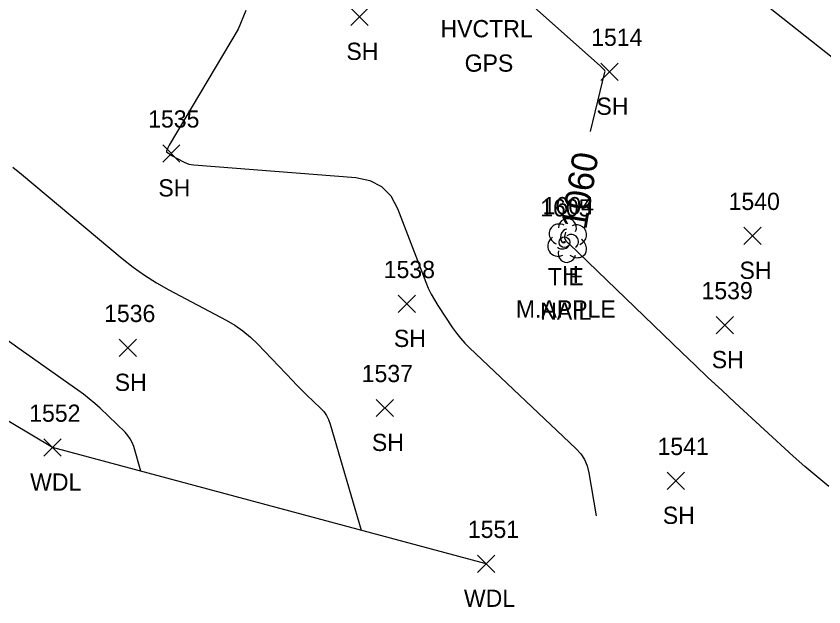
# Model space of a CAD drawing. Extents: x 1592612 to 1596497, y 111838 to 113741.
# Drawn here: x 1593027 to 1593120.8, y 113293.5 to 113362.1 of the extents above; entities that cross this region are included whole.
import ezdxf

# ---------------------------------------------------------------- set-up
doc = ezdxf.new("R2010")
doc.units = 0
for name, color, linetype in [('C_A', 7, 'Continuous'), ('C_C', 7, 'Continuous'), ('C_I', 7, 'Continuous'), ('CBP', 7, 'Continuous'), ('L_A', 7, 'Continuous'), ('L_C', 7, 'Continuous'), ('L_I', 7, 'Continuous'), ('L_TIC', 7, 'Continuous'), ('LAWA', 7, 'Continuous'), ('LSOGCMA', 7, 'Continuous'), ('LSOGCMA_T', 7, 'Continuous'), ('LSOGCMI', 7, 'Continuous'), ('LTD', 7, 'Continuous')]:
    doc.layers.add(name, color=color, linetype=linetype)

msp = doc.modelspace()

# ---------------------------------------------------------------- linework, layer by layer
at = {"layer": 'CBP'}
for radius in [0.625, 0.0833]:
    msp.add_circle((1593090.649, 113335.832), radius, dxfattribs=at)
at = {"layer": 'L_TIC'}
for points in [[(1593065.844, 113361.005), (1593067.844, 113363.005)], [(1593067.844, 113361.005), (1593065.844, 113363.005)], [(1593094.872, 113354.632), (1593096.872, 113356.632)], [(1593096.872, 113354.632), (1593094.872, 113356.632)], [(1593044.013, 113345.147), (1593046.013, 113347.147)], [(1593046.013, 113345.147), (1593044.013, 113347.147)], [(1593111.481, 113335.579), (1593113.481, 113337.579)], [(1593113.481, 113335.579), (1593111.481, 113337.579)], [(1593071.36, 113327.669), (1593073.36, 113329.669)], [(1593073.36, 113327.669), (1593071.36, 113329.669)], [(1593108.257, 113325.209), (1593110.257, 113327.209)], [(1593110.257, 113325.209), (1593108.257, 113327.209)], [(1593038.953, 113322.567), (1593040.953, 113324.567)], [(1593040.953, 113322.567), (1593038.953, 113324.567)], [(1593068.803, 113315.59), (1593070.803, 113317.59)], [(1593070.803, 113315.59), (1593068.803, 113317.59)], [(1593030.204, 113310.984), (1593032.204, 113312.984)], [(1593032.204, 113310.984), (1593030.204, 113312.984)], [(1593102.573, 113307.124), (1593104.573, 113309.124)], [(1593104.573, 113307.124), (1593102.573, 113309.124)], [(1593080.556, 113297.492), (1593082.556, 113299.492)], [(1593082.556, 113297.492), (1593080.556, 113299.492)]]:
    msp.add_lwpolyline(points, dxfattribs=at)
at = {"layer": 'LAWA'}
msp.add_lwpolyline([(1593081.556, 113298.492), (1593031.204, 113311.984), (1593004.196, 113328.084), (1592975.03, 113331.936), (1592955.15, 113341.657), (1592943.474, 113365.084), (1592935.771, 113387.596), (1592932.916, 113413.656)], dxfattribs=at)
at = {"layer": 'LSOGCMA'}
for points in [[(1593093.66, 113348.705), (1593095.344, 113355.593), (1593095.353, 113355.664), (1593095.344, 113355.73), (1593095.317, 113355.791), (1593095.272, 113355.846), (1593095.056, 113356.059), (1593095.002, 113356.111), (1593094.947, 113356.163), (1593094.892, 113356.215), (1593094.835, 113356.265), (1593081.553, 113368.117)], [(1593121.327, 113307.471), (1593119.927, 113308.618), (1593118.554, 113309.797), (1593117.206, 113311.006), (1593110.465, 113317.194), (1593108.902, 113318.638), (1593107.347, 113320.092), (1593105.8, 113321.556), (1593104.263, 113323.028), (1593091.183, 113335.635), (1593091.148, 113335.67), (1593091.112, 113335.704), (1593091.076, 113335.738), (1593091.04, 113335.772), (1593090.835, 113335.966), (1593090.83, 113335.971), (1593090.825, 113335.976), (1593090.821, 113335.982), (1593090.817, 113335.988), (1593090.801, 113336.012), (1593090.797, 113336.018), (1593090.794, 113336.024), (1593090.79, 113336.031), (1593090.788, 113336.037), (1593090.685, 113336.303), (1593090.671, 113336.35), (1593090.664, 113336.397), (1593090.665, 113336.445), (1593090.673, 113336.493), (1593090.801, 113337.014)]]:
    msp.add_lwpolyline(points, dxfattribs=at)
at = {"layer": 'LSOGCMI'}
for points in [[(1593113.604, 113363.735), (1593125.992, 113353.948)], [(1593053.675, 113362.732), (1593052.782, 113360.581), (1593044.775, 113347.096), (1593044.733, 113347.022), (1593044.692, 113346.947), (1593044.653, 113346.872), (1593044.617, 113346.795), (1593044.444, 113346.422), (1593044.431, 113346.38), (1593044.435, 113346.342), (1593044.454, 113346.31), (1593044.489, 113346.283), (1593044.684, 113346.172), (1593044.715, 113346.154), (1593044.745, 113346.134), (1593044.774, 113346.113), (1593044.803, 113346.09), (1593044.914, 113345.997), (1593044.942, 113345.975), (1593044.972, 113345.954), (1593045.002, 113345.934), (1593045.034, 113345.916), (1593046.519, 113345.129), (1593046.781, 113345.006), (1593047.051, 113344.912), (1593047.33, 113344.846), (1593047.618, 113344.809), (1593066.425, 113343.342), (1593068.06, 113343.013), (1593069.41, 113342.303), (1593070.476, 113341.211), (1593071.258, 113339.739), (1593074.543, 113331.201), (1593074.839, 113330.491), (1593075.172, 113329.8), (1593075.543, 113329.129), (1593075.952, 113328.477), (1593077.66, 113325.908), (1593078.103, 113325.279), (1593078.581, 113324.679), (1593079.091, 113324.107), (1593079.635, 113323.563), (1593091.983, 113311.881), (1593092.536, 113311.27), (1593092.971, 113310.597), (1593093.288, 113309.861), (1593093.486, 113309.062), (1593094.325, 113304.078)], [(1593026.597, 113344.543), (1593027.623, 113343.723), (1593039.288, 113333.962), (1593040.573, 113332.942), (1593041.905, 113331.994), (1593043.286, 113331.117), (1593044.714, 113330.311), (1593051.36, 113326.785), (1593052.366, 113326.2), (1593053.314, 113325.539), (1593054.206, 113324.804), (1593055.042, 113323.994), (1593059.107, 113319.724), (1593059.498, 113319.319), (1593059.893, 113318.918), (1593060.293, 113318.522), (1593060.698, 113318.13), (1593062.327, 113316.574), (1593062.703, 113316.165), (1593063.016, 113315.719), (1593063.268, 113315.235), (1593063.456, 113314.714), (1593067.05, 113302.379)], [(1593041.481, 113309.23), (1593040.641, 113312.115), (1593040.473, 113312.579), (1593040.249, 113313.009), (1593039.971, 113313.406), (1593039.636, 113313.769), (1593036.732, 113316.545), (1593036.117, 113317.111), (1593035.483, 113317.653), (1593034.828, 113318.171), (1593034.154, 113318.665), (1593027.189, 113323.573), (1593025.812, 113324.567)]]:
    msp.add_lwpolyline(points, dxfattribs=at)
at = {"layer": 'LTD'}
msp.add_line((1593090.941, 113336.083), (1593090.941, 113336.083), dxfattribs=at)
msp.add_line((1593090.941, 113336.083), (1593090.941, 113336.083), dxfattribs=at)
msp.add_arc((1593090.988, 113337.517), 1.047, 335.52715, 180.95627, dxfattribs=at)
for centre, major_axis, ratio, start_param, end_param in [((1593090.149, 113336.749), (1.21, -0.512), 0.895232, 1.570796, 4.712389), ((1593091.982, 113336.666), (-1.141, -0.483), 0.949671, 1.570796, 4.712389), ((1593090.732, 113336.541), (-0.208, -0.792), 0.645439, 3.141593, 6.283185), ((1593091.441, 113335.916), (-0.5, 0.667), 0.989748, 3.141593, 6.283185), ((1593089.858, 113335.374), (0.584, -1.042), 0.959034, 3.141593, 6.283185), ((1593091.941, 113335.25), (-1.09, 0.792), 0.841452, 1.570796, 4.712389), ((1593090.483, 113335.333), (-0.625, -0.083), 0.423636, 0, 3.141593), ((1593090.941, 113334.583), (0.265, 1.061), 0.942809, 1.570796, 4.712389)]:
    msp.add_ellipse(centre, major_axis=major_axis, ratio=ratio, start_param=start_param, end_param=end_param, dxfattribs=at)

# ---------------------------------------------------------------- texts
at = {"layer": 'C_A'}
for s, p in [('HVCTRL', (1593076.256, 113359.637)), ('HVCTRL', (1593076.265, 113359.633)), ('TIE', (1593088.728, 113330.832))]:
    msp.add_text(s, height=2, dxfattribs=at).set_placement(p)
at = {"layer": 'C_C'}
for s, p in [('GPS', (1593079.059, 113355.637)), ('NAIL', (1593087.83, 113326.832))]:
    msp.add_text(s, height=2, dxfattribs=at).set_placement(p)
at = {"layer": 'C_I'}
msp.add_text('1605', height=2, dxfattribs=at).set_placement((1593087.83, 113338.832))
at = {"layer": 'L_A'}
for s, p in [('SH', (1593065.333, 113357.005)), ('SH', (1593094.36, 113350.632)), ('SH', (1593043.502, 113341.147)), ('SH', (1593110.969, 113331.579)), ('H', (1593090.374, 113331.083)), ('SH', (1593070.848, 113323.669)), ('SH', (1593107.745, 113321.209)), ('SH', (1593038.441, 113318.567)), ('SH', (1593068.291, 113311.59)), ('WDL', (1593028.621, 113306.984)), ('SH', (1593102.061, 113303.124)), ('WDL', (1593078.973, 113293.492))]:
    msp.add_text(s, height=2, dxfattribs=at).set_placement(p)
at = {"layer": 'L_C'}
msp.add_text('M.APPLE', height=2, dxfattribs=at).set_placement((1593085.004, 113327.083))
at = {"layer": 'L_I'}
for s, p in [('1514', (1593093.746, 113358.632)), ('1535', (1593042.321, 113349.147)), ('1540', (1593109.702, 113339.579)), ('1604', (1593088.122, 113339.083)), ('1538', (1593069.667, 113331.669)), ('1539', (1593106.557, 113329.209)), ('1536', (1593037.204, 113326.567)), ('1537', (1593067.11, 113319.59)), ('1552', (1593028.511, 113314.984)), ('1541', (1593101.447, 113311.124)), ('1551', (1593079.43, 113301.492))]:
    msp.add_text(s, height=2, dxfattribs=at).set_placement(p)
at = {"layer": 'LSOGCMA_T'}
msp.add_text('1060', height=3, rotation=80.70818, dxfattribs=at).set_placement((1593093.175, 113337.2))

doc.saveas('drawing.dxf')
